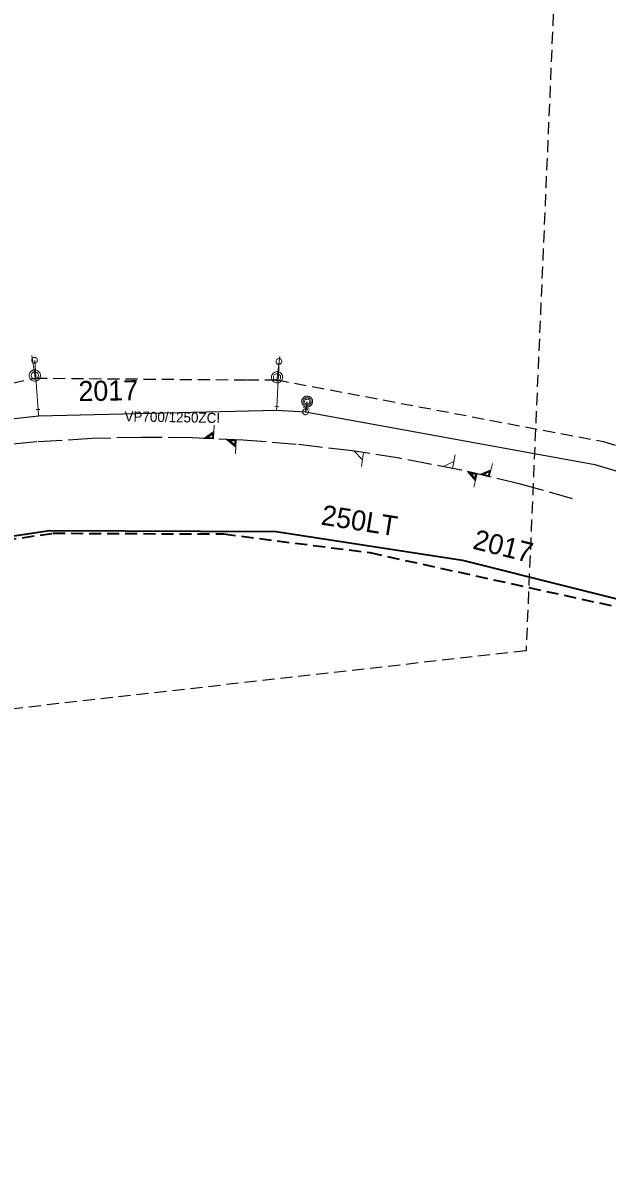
# Model space of a CAD drawing. Extents: x -740786 to -740000, y -1046854 to -1046100.
# Drawn here: x -740508.6 to -740462.1, y -1046832.5 to -1046741 of the extents above; entities that cross this region are included whole.
import ezdxf

# ---------------------------------------------------------------- set-up
doc = ezdxf.new("R2010")
doc.units = 0
doc.header["$LTSCALE"] = 0.32
doc.linetypes.add('LONG_DASHED', pattern=[7.5, 6, -1.5])
doc.linetypes.add('MEDIUM_DASHED', pattern=[4.5, 3, -1.5])
doc.layers.add('1', color=7, linetype='Continuous')
doc.layers.add('15', color=7, linetype='Continuous')
for name, color, linetype, lineweight in [('18', 7, 'Continuous', 13), ('20', 7, 'LONG_DASHED', 25), ('63', 7, 'MEDIUM_DASHED', 25), ('8', 7, 'Continuous', 13)]:
    doc.layers.add(name, color=color, linetype=linetype, lineweight=lineweight)

msp = doc.modelspace()

# ---------------------------------------------------------------- linework, layer by layer
at = {"layer": '18'}
for points in [[(-740493.354, -1046773.008), (-740493.403, -1046774.103), (-740494.172, -1046774.069), (-740493.377, -1046773.526)], [(-740493.432, -1046773.641), (-740493.451, -1046774.057), (-740494.016, -1046774.032), (-740493.432, -1046773.64)], [(-740493.483, -1046773.723), (-740493.496, -1046774.014), (-740493.867, -1046773.997), (-740493.482, -1046773.723)], [(-740491.656, -1046775.274), (-740491.607, -1046774.179), (-740492.378, -1046774.145), (-740491.633, -1046774.756)], [(-740491.679, -1046774.636), (-740491.66, -1046774.221), (-740492.225, -1046774.196), (-740491.679, -1046774.637)], [(-740491.722, -1046774.55), (-740491.709, -1046774.259), (-740492.08, -1046774.243), (-740491.721, -1046774.55)], [(-740481.627, -1046776.301), (-740481.458, -1046775.201), (-740482.209, -1046775.086), (-740481.547, -1046775.787)], [(-740474.161, -1046775.387), (-740474.369, -1046776.464), (-740475.129, -1046776.318), (-740474.261, -1046775.898)], [(-740472.674, -1046777.958), (-740472.422, -1046776.891), (-740473.172, -1046776.714), (-740472.555, -1046777.454)], [(-740472.577, -1046777.327), (-740472.482, -1046776.922), (-740473.031, -1046776.792), (-740472.578, -1046777.328)], [(-740471.193, -1046776.058), (-740471.446, -1046777.125), (-740472.195, -1046776.948), (-740471.312, -1046776.563)], [(-740471.388, -1046776.666), (-740471.484, -1046777.071), (-740472.035, -1046776.94), (-740471.388, -1046776.665)], [(-740471.453, -1046776.737), (-740471.52, -1046777.02), (-740471.882, -1046776.934), (-740471.452, -1046776.737)], [(-740472.604, -1046777.234), (-740472.537, -1046776.951), (-740472.898, -1046776.866), (-740472.603, -1046777.235)]]:
    msp.add_lwpolyline(points, dxfattribs=at)
at = {"layer": '20'}
msp.add_lwpolyline([(-740464.809, -1046778.87), (-740468.967, -1046777.712), (-740473.69, -1046776.594), (-740478.593, -1046775.649), (-740482.353, -1046775.071), (-740486.829, -1046774.544), (-740491.064, -1046774.206), (-740495.107, -1046774.028), (-740499.182, -1046773.989), (-740503.074, -1046774.085), (-740507.47, -1046774.35), (-740512.021, -1046774.8), (-740516.44, -1046775.411), (-740520.27, -1046776.08), (-740526.17, -1046774.44)], dxfattribs=at)
msp.add_lwpolyline([(-740464.809, -1046778.87), (-740468.967, -1046777.712), (-740473.69, -1046776.594), (-740478.593, -1046775.649), (-740482.353, -1046775.071), (-740486.829, -1046774.544), (-740491.064, -1046774.206), (-740495.107, -1046774.028), (-740499.182, -1046773.989), (-740503.074, -1046774.085), (-740507.47, -1046774.35), (-740512.021, -1046774.8), (-740516.44, -1046775.411), (-740520.27, -1046776.08), (-740526.17, -1046774.44)], dxfattribs=at)
at = {"layer": '63'}
msp.add_lwpolyline([(-740455.336, -1046482.714), (-740468.522, -1046790.977), (-740468.522, -1046790.979), (-740468.523, -1046790.981), (-740468.524, -1046790.982), (-740468.525, -1046790.984), (-740468.527, -1046790.985), (-740468.529, -1046790.986), (-740468.531, -1046790.986), (-740589.04, -1046804.624), (-740589.042, -1046804.624), (-740589.044, -1046804.624), (-740589.046, -1046804.623), (-740589.047, -1046804.622), (-740589.049, -1046804.621), (-740589.05, -1046804.619), (-740589.05, -1046804.617), (-740589.051, -1046804.615), (-740596.533, -1046717.763), (-740626.694, -1046502.274)], dxfattribs=at)
at = {"layer": '8'}
for p, q in [((-740507.64, -1046769.07), (-740507.87, -1046767.462)), ((-740507.612, -1046769.267), (-740507.64, -1046769.07)), ((-740507.239, -1046771.762), (-740507.543, -1046771.778)), ((-740507.359, -1046772.265), (-740507.385, -1046771.77)), ((-740488.212, -1046771.544), (-740488.514, -1046771.506)), ((-740486.266, -1046771.616), (-740485.761, -1046771.729))]:
    msp.add_line(p, q, dxfattribs=at)
at = {"layer": '8', "lineweight": 25}
msp.add_line((-740486.079, -1046771.964), (-740486.013, -1046771.673), dxfattribs=at)
at = {"layer": '8'}
for points in [[(-740507.677, -1046767.614), (-740507.728, -1046767.623), (-740507.777, -1046767.645), (-740507.819, -1046767.675), (-740507.853, -1046767.716), (-740507.877, -1046767.763), (-740507.89, -1046767.814), (-740507.891, -1046767.866), (-740507.881, -1046767.917), (-740507.858, -1046767.965), (-740507.825, -1046768.007), (-740507.784, -1046768.039), (-740507.737, -1046768.062), (-740507.686, -1046768.073), (-740507.633, -1046768.073), (-740507.582, -1046768.061), (-740507.536, -1046768.037), (-740507.495, -1046768.004), (-740507.463, -1046767.962), (-740507.442, -1046767.915), (-740507.431, -1046767.863), (-740507.433, -1046767.811), (-740507.446, -1046767.759), (-740507.471, -1046767.713), (-740507.506, -1046767.673), (-740507.548, -1046767.643), (-740507.597, -1046767.622), (-740507.649, -1046767.614)], [(-740488.19, -1046767.707), (-740488.243, -1046767.711), (-740488.293, -1046767.727), (-740488.339, -1046767.752), (-740488.377, -1046767.789), (-740488.406, -1046767.832), (-740488.425, -1046767.882), (-740488.432, -1046767.933), (-740488.427, -1046767.986), (-740488.411, -1046768.035), (-740488.383, -1046768.081), (-740488.345, -1046768.118), (-740488.302, -1046768.146), (-740488.251, -1046768.163), (-740488.2, -1046768.168), (-740488.147, -1046768.163), (-740488.098, -1046768.144), (-740488.054, -1046768.116), (-740488.017, -1046768.078), (-740487.991, -1046768.033), (-740487.975, -1046767.983), (-740487.97, -1046767.931), (-740487.978, -1046767.878), (-740487.998, -1046767.829), (-740488.028, -1046767.786), (-740488.066, -1046767.751), (-740488.112, -1046767.725), (-740488.162, -1046767.711)], [(-740507.193, -1046769.059), (-740507.199, -1046768.986), (-740507.217, -1046768.915), (-740507.246, -1046768.848), (-740507.286, -1046768.787), (-740507.335, -1046768.732), (-740507.392, -1046768.687), (-740507.456, -1046768.652), (-740507.525, -1046768.627), (-740507.597, -1046768.614), (-740507.671, -1046768.613), (-740507.743, -1046768.624), (-740507.813, -1046768.647), (-740507.877, -1046768.68), (-740507.936, -1046768.724), (-740507.987, -1046768.777), (-740508.028, -1046768.837), (-740508.059, -1046768.904), (-740508.079, -1046768.974), (-740508.087, -1046769.047), (-740508.083, -1046769.12), (-740508.067, -1046769.191), (-740508.04, -1046769.259), (-740508.002, -1046769.322), (-740507.954, -1046769.377), (-740507.898, -1046769.424), (-740507.835, -1046769.461), (-740507.767, -1046769.488), (-740507.695, -1046769.503), (-740507.622, -1046769.506), (-740507.549, -1046769.497), (-740507.479, -1046769.476), (-740507.413, -1046769.444), (-740507.353, -1046769.402), (-740507.301, -1046769.351), (-740507.258, -1046769.291), (-740507.225, -1046769.226), (-740507.204, -1046769.156), (-740507.194, -1046769.084)], [(-740507.354, -1046769.059), (-740507.36, -1046769.001), (-740507.378, -1046768.945), (-740507.406, -1046768.894), (-740507.445, -1046768.85), (-740507.491, -1046768.814), (-740507.544, -1046768.789), (-740507.601, -1046768.775), (-740507.66, -1046768.773), (-740507.717, -1046768.783), (-740507.772, -1046768.805), (-740507.821, -1046768.837), (-740507.862, -1046768.878), (-740507.894, -1046768.927), (-740507.916, -1046768.982), (-740507.926, -1046769.039), (-740507.924, -1046769.098), (-740507.91, -1046769.155), (-740507.885, -1046769.208), (-740507.849, -1046769.254), (-740507.805, -1046769.293), (-740507.754, -1046769.321), (-740507.698, -1046769.339), (-740507.64, -1046769.345), (-740507.582, -1046769.339), (-740507.526, -1046769.322), (-740507.475, -1046769.293), (-740507.431, -1046769.254), (-740507.396, -1046769.208), (-740507.371, -1046769.155), (-740507.357, -1046769.098)], [(-740487.902, -1046769.199), (-740487.909, -1046769.126), (-740487.927, -1046769.055), (-740487.956, -1046768.988), (-740487.995, -1046768.927), (-740488.044, -1046768.872), (-740488.102, -1046768.827), (-740488.166, -1046768.792), (-740488.235, -1046768.767), (-740488.307, -1046768.754), (-740488.38, -1046768.753), (-740488.453, -1046768.764), (-740488.522, -1046768.787), (-740488.587, -1046768.82), (-740488.646, -1046768.864), (-740488.696, -1046768.917), (-740488.738, -1046768.977), (-740488.769, -1046769.044), (-740488.789, -1046769.114), (-740488.797, -1046769.187), (-740488.793, -1046769.26), (-740488.777, -1046769.331), (-740488.75, -1046769.399), (-740488.712, -1046769.462), (-740488.664, -1046769.517), (-740488.608, -1046769.564), (-740488.544, -1046769.601), (-740488.477, -1046769.628), (-740488.405, -1046769.643), (-740488.331, -1046769.646), (-740488.259, -1046769.637), (-740488.189, -1046769.616), (-740488.123, -1046769.584), (-740488.063, -1046769.542), (-740488.011, -1046769.491), (-740487.968, -1046769.431), (-740487.934, -1046769.366), (-740487.914, -1046769.296), (-740487.904, -1046769.224)], [(-740488.064, -1046769.199), (-740488.07, -1046769.141), (-740488.088, -1046769.085), (-740488.115, -1046769.034), (-740488.155, -1046768.99), (-740488.201, -1046768.954), (-740488.254, -1046768.929), (-740488.311, -1046768.915), (-740488.37, -1046768.913), (-740488.427, -1046768.923), (-740488.482, -1046768.945), (-740488.531, -1046768.977), (-740488.571, -1046769.018), (-740488.603, -1046769.067), (-740488.625, -1046769.122), (-740488.636, -1046769.179), (-740488.634, -1046769.238), (-740488.62, -1046769.295), (-740488.595, -1046769.348), (-740488.559, -1046769.394), (-740488.515, -1046769.433), (-740488.463, -1046769.461), (-740488.407, -1046769.479), (-740488.35, -1046769.485), (-740488.292, -1046769.479), (-740488.236, -1046769.462), (-740488.184, -1046769.433), (-740488.141, -1046769.394), (-740488.106, -1046769.348), (-740488.081, -1046769.295), (-740488.066, -1046769.238)], [(-740485.63, -1046771.144), (-740485.636, -1046771.083), (-740485.654, -1046771.023), (-740485.683, -1046770.968), (-740485.722, -1046770.92), (-740485.769, -1046770.88), (-740485.823, -1046770.85), (-740485.882, -1046770.83), (-740485.944, -1046770.823), (-740486.006, -1046770.827), (-740486.066, -1046770.843), (-740486.121, -1046770.871), (-740486.171, -1046770.908), (-740486.212, -1046770.955), (-740486.244, -1046771.008), (-740486.264, -1046771.067), (-740486.274, -1046771.128), (-740486.271, -1046771.19), (-740486.256, -1046771.25), (-740486.23, -1046771.307), (-740486.194, -1046771.357), (-740486.148, -1046771.4), (-740486.096, -1046771.432), (-740486.038, -1046771.455), (-740485.977, -1046771.465), (-740485.915, -1046771.464), (-740485.854, -1046771.451), (-740485.797, -1046771.426), (-740485.746, -1046771.391), (-740485.702, -1046771.347), (-740485.668, -1046771.295), (-740485.644, -1046771.238), (-740485.632, -1046771.177)], [(-740485.744, -1046771.144), (-740485.75, -1046771.095), (-740485.767, -1046771.048), (-740485.795, -1046771.007), (-740485.833, -1046770.974), (-740485.877, -1046770.95), (-740485.925, -1046770.938), (-740485.975, -1046770.937), (-740486.023, -1046770.949), (-740486.068, -1046770.971), (-740486.106, -1046771.004), (-740486.135, -1046771.044), (-740486.154, -1046771.091), (-740486.161, -1046771.14), (-740486.156, -1046771.19), (-740486.139, -1046771.237), (-740486.112, -1046771.279), (-740486.075, -1046771.313), (-740486.032, -1046771.337), (-740485.984, -1046771.351), (-740485.934, -1046771.352), (-740485.885, -1046771.342), (-740485.84, -1046771.32), (-740485.801, -1046771.288), (-740485.771, -1046771.249), (-740485.752, -1046771.203), (-740485.744, -1046771.153)], [(-740485.847, -1046771.967), (-740485.85, -1046771.915), (-740485.865, -1046771.864), (-740485.89, -1046771.818), (-740485.926, -1046771.779), (-740485.969, -1046771.749), (-740486.018, -1046771.73), (-740486.07, -1046771.722), (-740486.122, -1046771.726), (-740486.172, -1046771.742), (-740486.218, -1046771.769), (-740486.255, -1046771.806), (-740486.284, -1046771.849), (-740486.302, -1046771.899), (-740486.308, -1046771.951), (-740486.303, -1046772.003), (-740486.285, -1046772.053), (-740486.258, -1046772.097), (-740486.22, -1046772.135), (-740486.176, -1046772.161), (-740486.126, -1046772.179), (-740486.074, -1046772.184), (-740486.021, -1046772.177), (-740485.972, -1046772.158), (-740485.928, -1046772.129), (-740485.893, -1046772.091), (-740485.866, -1046772.045), (-740485.851, -1046771.995)]]:
    msp.add_lwpolyline(points, close=True, dxfattribs=at)
for points in [[(-740488.377, -1046769.408), (-740488.35, -1046769.21), (-740488.116, -1046767.541)], [(-740507.385, -1046771.77), (-740507.502, -1046770.028), (-740507.651, -1046767.844)], [(-740488.394, -1046771.822), (-740488.357, -1046771.526), (-740488.191, -1046767.939)], [(-740485.517, -1046771.136), (-740485.519, -1046771.091), (-740485.526, -1046771.046), (-740485.538, -1046771.001), (-740485.554, -1046770.959), (-740485.575, -1046770.918), (-740485.6, -1046770.879), (-740485.629, -1046770.844), (-740485.661, -1046770.811), (-740485.697, -1046770.783), (-740485.735, -1046770.758), (-740485.776, -1046770.737), (-740485.819, -1046770.72), (-740485.863, -1046770.708), (-740485.908, -1046770.701), (-740485.954, -1046770.699), (-740486, -1046770.701), (-740486.045, -1046770.708), (-740486.089, -1046770.72), (-740486.132, -1046770.737), (-740486.173, -1046770.758), (-740486.211, -1046770.783), (-740486.247, -1046770.811), (-740486.279, -1046770.844), (-740486.308, -1046770.879), (-740486.333, -1046770.918), (-740486.354, -1046770.959), (-740486.37, -1046771.001), (-740486.382, -1046771.046), (-740486.389, -1046771.091), (-740486.392, -1046771.137), (-740486.389, -1046771.182), (-740486.382, -1046771.227), (-740486.37, -1046771.272), (-740486.354, -1046771.314), (-740486.333, -1046771.355), (-740486.308, -1046771.394), (-740486.279, -1046771.429), (-740486.247, -1046771.462), (-740486.211, -1046771.49), (-740486.173, -1046771.515), (-740486.132, -1046771.536), (-740486.089, -1046771.553), (-740486.045, -1046771.564), (-740486, -1046771.572), (-740485.954, -1046771.574), (-740485.908, -1046771.572), (-740485.863, -1046771.564), (-740485.819, -1046771.553), (-740485.776, -1046771.536), (-740485.735, -1046771.515), (-740485.697, -1046771.49), (-740485.661, -1046771.462), (-740485.629, -1046771.429), (-740485.6, -1046771.394), (-740485.575, -1046771.355), (-740485.554, -1046771.314), (-740485.538, -1046771.272), (-740485.526, -1046771.227), (-740485.519, -1046771.182), (-740485.517, -1046771.137)]]:
    msp.add_lwpolyline(points, dxfattribs=at)
at = {"layer": '8', "linetype": 'MEDIUM_DASHED', "lineweight": 25}
msp.add_lwpolyline([(-740545.05, -1046777.37), (-740523.519, -1046772.752), (-740507.612, -1046769.267), (-740490.756, -1046769.41), (-740488.377, -1046769.408), (-740462.339, -1046774.323), (-740444.309, -1046779.935), (-740440.26, -1046781.19), (-740426.241, -1046786.116), (-740418.958, -1046789.301), (-740410.476, -1046793.296), (-740406.559, -1046795.41)], dxfattribs=at)
at = {"layer": '8', "lineweight": 25}
for points in [[(-740486.013, -1046771.673), (-740485.949, -1046771.212), (-740485.947, -1046771.147)], [(-740545.125, -1046777.451), (-740544.864, -1046777.371), (-740542.545, -1046776.91), (-740535.611, -1046776.028), (-740527.396, -1046775.438), (-740522.967, -1046773.997), (-740507.359, -1046772.265), (-740488.394, -1046771.822), (-740486.079, -1046771.964)], [(-740486.079, -1046771.964), (-740463.034, -1046776.143), (-740441, -1046782.756), (-740426.947, -1046787.97), (-740407.815, -1046797.029)]]:
    msp.add_lwpolyline(points, dxfattribs=at)
at = {"layer": '8', "lineweight": 35}
msp.add_lwpolyline([(-740529.958, -1046784.902), (-740529.552, -1046784.845), (-740506.48, -1046781.401), (-740488.414, -1046781.484), (-740473.581, -1046783.776), (-740456.01, -1046788.168), (-740450.964, -1046789.642), (-740447.322, -1046790.706), (-740429.436, -1046796.984), (-740404.93, -1046808.509), (-740390.532, -1046816.698), (-740374.355, -1046825.651)], dxfattribs=at)
at = {"layer": '8', "linetype": 'MEDIUM_DASHED', "lineweight": 35}
msp.add_lwpolyline([(-740530.03, -1046785.06), (-740506.197, -1046781.624), (-740492.614, -1046781.683), (-740480.958, -1046783.167), (-740461.337, -1046787.473), (-740450.943, -1046790.142), (-740447.603, -1046790.999), (-740434.64, -1046795.39), (-740429.405, -1046797.359), (-740416.811, -1046803.079), (-740374.397, -1046826.222), (-740362.605, -1046832.504)], dxfattribs=at)

# ---------------------------------------------------------------- texts
at = {"layer": '1'}
msp.add_text('VP700/1250ZCI ', height=0.8, rotation=359, dxfattribs=at).set_placement((-740500.504, -1046772.711))
at = {"layer": '15'}
for s, rotation, p in [('2017', 1, (-740504.155, -1046771.105)), ('250LT ', 351, (-740484.909, -1046780.928)), ('2017', 346, (-740472.84, -1046782.843))]:
    msp.add_text(s, height=1.6, rotation=rotation, dxfattribs=at).set_placement(p)

doc.saveas('drawing.dxf')
